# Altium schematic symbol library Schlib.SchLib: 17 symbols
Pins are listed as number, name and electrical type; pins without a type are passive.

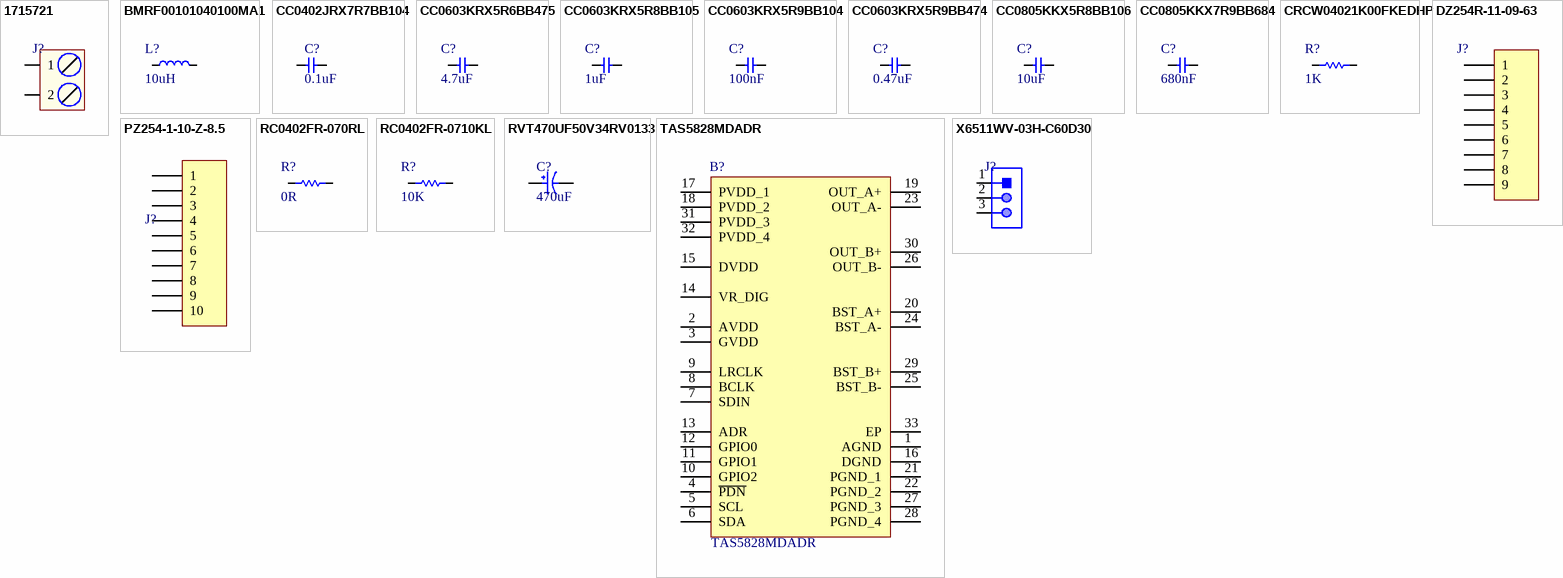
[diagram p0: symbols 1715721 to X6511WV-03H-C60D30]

## 1715721
designator J?
TERM BLK 2P SIDE ENT 5.08MM PCB; Manufacturer: Phoenix Contact; Manufacturer Part Number: 1715721; Item Type: Terminal Blocks
footprint 1715721
pins: 1, 2

## BMRF00101040100MA1
designator L?, comment 10uH
6.5A 10uH Shielded inductor ±20% 7A Power Inductors ROHS; Manufacturer: Chilisin Elec; Manufacturer Part Number: BMRF00101040100MA1
footprint BMRF00101040100MA1
pins: 1, 2

## CC0402JRX7R7BB104
designator C?, comment 0.1uF
CAP CER 0.1UF 16V X7R 0402; Manufacturer: Yageo; Manufacturer Part Number: CC0402JRX7R7BB104; Material: 4241ConductorMaterial; Value: 100nF; Tolerance: 5%; Item Type: Capacitor
footprint Cap-0402
pins: 1, 2

## CC0603KRX5R6BB475
designator C?, comment 4.7uF
CAP CER 4.7UF 10V X5R 0603; Manufacturer: Yageo; Manufacturer Part Number: CC0603KRX5R6BB475; Tolerance: 10%; Item Type: Capacitor
footprint Cap-0603
pins: 1, 2

## CC0603KRX5R8BB105
designator C?, comment 1uF
CAP CER 1UF 25V X5R 0603; Manufacturer: Yageo; Manufacturer Part Number: CC0603KRX5R8BB105; Tolerance: 10%; Item Type: Capacitor
footprint Cap-0603
pins: 1, 2

## CC0603KRX5R9BB104
designator C?, comment 100nF
CAP CER 0.1UF 50V X5R 0603; Manufacturer: Yageo; Manufacturer Part Number: CC0603KRX5R9BB104; Tolerance: 10%; Item Type: Capacitor
footprint Cap-0603
pins: 1, 2

## CC0603KRX5R9BB474
designator C?, comment 0.47uF
CAP CER 0.47UF 50V X5R 0603; Manufacturer: Yageo; Manufacturer Part Number: CC0603KRX5R9BB474; Capacitance: 470nF; Tolerance: 10%; Item Type: Capacitor
footprint Cap-0603
pins: 1, 2

## CC0805KKX5R8BB106
designator C?, comment 10uF
CAP CER 10UF 25V X5R 0805; Manufacturer: Yageo; Manufacturer Part Number: CC0805KKX5R8BB106; Tolerance: 10%; Item Type: Capacitor
footprint Cap-0805 (SMD 0805)
pins: 1, 2

## CC0805KKX7R9BB684
designator C?, comment 680nF
50V 680nF X7R ±10% 0805 Multilayer Ceramic Capacitors MLCC - SMD/SMT ROHS; Manufacturer: YAGEO; Manufacturer Part Number: CC0805KKX7R9BB684; Item Type: Cap
footprint Cap-0805 (SMD 0805)
pins: 1, 2

## CRCW04021K00FKEDHP
designator R?, comment 1K
RES SMD 1K OHM 1% 1/5W 0402; Manufacturer: Vishay Dale; Manufacturer Part Number: CRCW04021K00FKEDHP; Resistance: 1kR; Temperature Coefficient: 100ppm/°C; Power Rating: 125mW; Voltage Rating: 50V
footprint Res-0402
pins: 1, 2

## DZ254R-11-09-63
designator J?
3A Straight Square Pins 2.54mm 6mm 3mm 9 2.54mm 单排 1x9P Plugin,P=2.54mm Pin Headers ROHS; Manufacturer Part Number: DZ254R-11-09-63; Manufacturer: DEALON; Item Type: Male Header
footprint HDR1X9
pins: 1, 2, 3, 4, 5, 6, 7, 8, 9

## PZ254-1-10-Z-8.5
designator J?
3A Direct Insert Policy 2.5mm 260℃@10S 10P 6mm -40℃~+105℃ 3mm 2.54mm Single Row Black Brass 1x10P Plugin,P=2.54mm Pin Headers ROHS; Manufacturer: HCTL; Manufacturer Part Number: PZ254-1-10-Z-8.5; Item Type: Header
footprint PZ254-1-10-Z-8.5
pins: 1, 2, 3, 4, 5, 6, 7, 8, 9, 10

## RC0402FR-070RL
designator R?, comment 0R
RES 0 OHM JUMPER 1/16W 0402; Manufacturer: Yageo; Manufacturer Part Number: RC0402FR-070RL; Item Type: Resistors; Tolerance: 1%; Power Rating: 62.5mW; Voltage Rating: 50V; Temperature Coefficient: 200ppm/°C; Max Power Dissipation: 63mW
footprint Res-0402
pins: 1, 2

## RC0402FR-0710KL
designator R?, comment 10K
RES 10K OHM 1% 1/16W 0402; Manufacturer: Yageo; Manufacturer Part Number: RC0402FR-0710KL; Resistance: 10kR; Voltage Rating (DC): 50V; Temperature Coefficient: 100ppm/°C; Power Rating: 62.5mW; Max Power Dissipation: 63mW; Item Type: Resistor
footprint Res-0402
pins: 1, 2

## RVT470UF50V34RV0133
designator C?, comment 470uF
470uF 50V 50mA@120Hz ±20% SMD,D12.5xL13.5mm Aluminum Electrolytic Capacitors - SMD ROHS; Manufacturer: KNSCHA; Manufacturer Part Number: RVT470UF50V34RV0133
footprint RVT470UF50V34RV0133
pins: 1, 2

## TAS5828MDADR
designator B?
Audio Amplifiers 50-W stereo, digital input, high-performance, closed-loop, Class-D, with integrated audio processor 32-HTSSOP -40 to 85; Manufacturer_Name: Texas Instruments; Geometry.Height: 1.15mm
footprint SOP65P810X115-33M
pins: 1 AGND, 2 AVDD, 3 GVDD, 4 ~{PDN}, 5 SCL, 6 SDA, 7 SDIN, 8 BCLK, 9 LRCLK, 10 GPIO2, 11 GPIO1, 12 GPIO0, 13 ADR, 14 VR_DIG, 15 DVDD, 16 DGND, 17 PVDD_1, 18 PVDD_2, 19 OUT_A+, 20 BST_A+, 21 PGND_1, 22 PGND_2, 23 OUT_A-, 24 BST_A-, 25 BST_B-, 26 OUT_B-, 27 PGND_3, 28 PGND_4, 29 BST_B+, 30 OUT_B+, 31 PVDD_3, 32 PVDD_4, 33 EP

## X6511WV-03H-C60D30
designator J?
Gold 250V 3A Straight Square Pins 2.5mm 3P 260℃ 6mm -40℃~+105℃ 3mm 2.54mm Plugin Black Brass 1x3P Plugin,P=2.54mm Pin Headers ROHS; Manufacturer: XKB; Manufacturer Part Number: X6511WV-03H-C60D30; Item Type: Male Header
footprint HDR1X3_ (Connector; Header; 3 Position)
pins: 1, 2, 3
